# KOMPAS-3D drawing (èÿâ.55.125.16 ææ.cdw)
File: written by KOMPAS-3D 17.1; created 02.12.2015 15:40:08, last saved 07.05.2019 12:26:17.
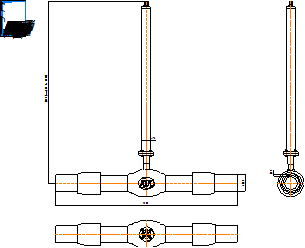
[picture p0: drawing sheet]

Sheet 1: A4, portrait

Title block, sheet 1: name: КШГ.55.125.16 СС; material: Внимание! Данный продукт является объектом авторского права ООО «Торговый Дом АДЛ». / Запрещается изменение, копирование, распространение / (в том числе путем копирования на другие сайты и ресурсы в Интернете) / или любое иное использование информации и объектов без предварительного / согласия правообладателя (ООО «Торговый Дом АДЛ»).; sheets: 1; organisation: ООО "Торговый дом АДЛ"; sheet format: A4; stored path: C:\Users\kka\KOMPAS_Work\Модели кранов для исследований\DN50\С удлинением\КШГ.32.050.40 СС ГЧ _ Шаровой кран БИВАЛ Ду50 Ру4 МПа редуцированный под приварку, с удлинением штока H=1100.cdw; drawn by: Климкович К.А.; drawn by, date: 07.12.16

Views: Вид 1, Проекционный вид 2
Referenced files in C:\Users\kka\KOMPAS_Work\Модели кранов для исследований\DN80\С удлинением\: КШТ.22.080.25 СС.a3d
Referenced files in C:\Users\kka\KOMPAS_Work\Модели кранов для исследований\DN150\С удлинением\: КШТ.22.150.25 СС.a3d, КШГ.35.125.25 СС Lстр600.a3d, КШГ.35.125.25 СС Lстр600.a3d!Деталь (локальная).m3d
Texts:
  Klimkovich
  ADL
  (от 480 до 5000)
Dimensions and other numbers on the sheet: 76; 140; 1500; 15,7; 1:1; 1; 07.12.16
